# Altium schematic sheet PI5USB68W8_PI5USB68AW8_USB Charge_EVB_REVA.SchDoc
size 246 x 182 mm
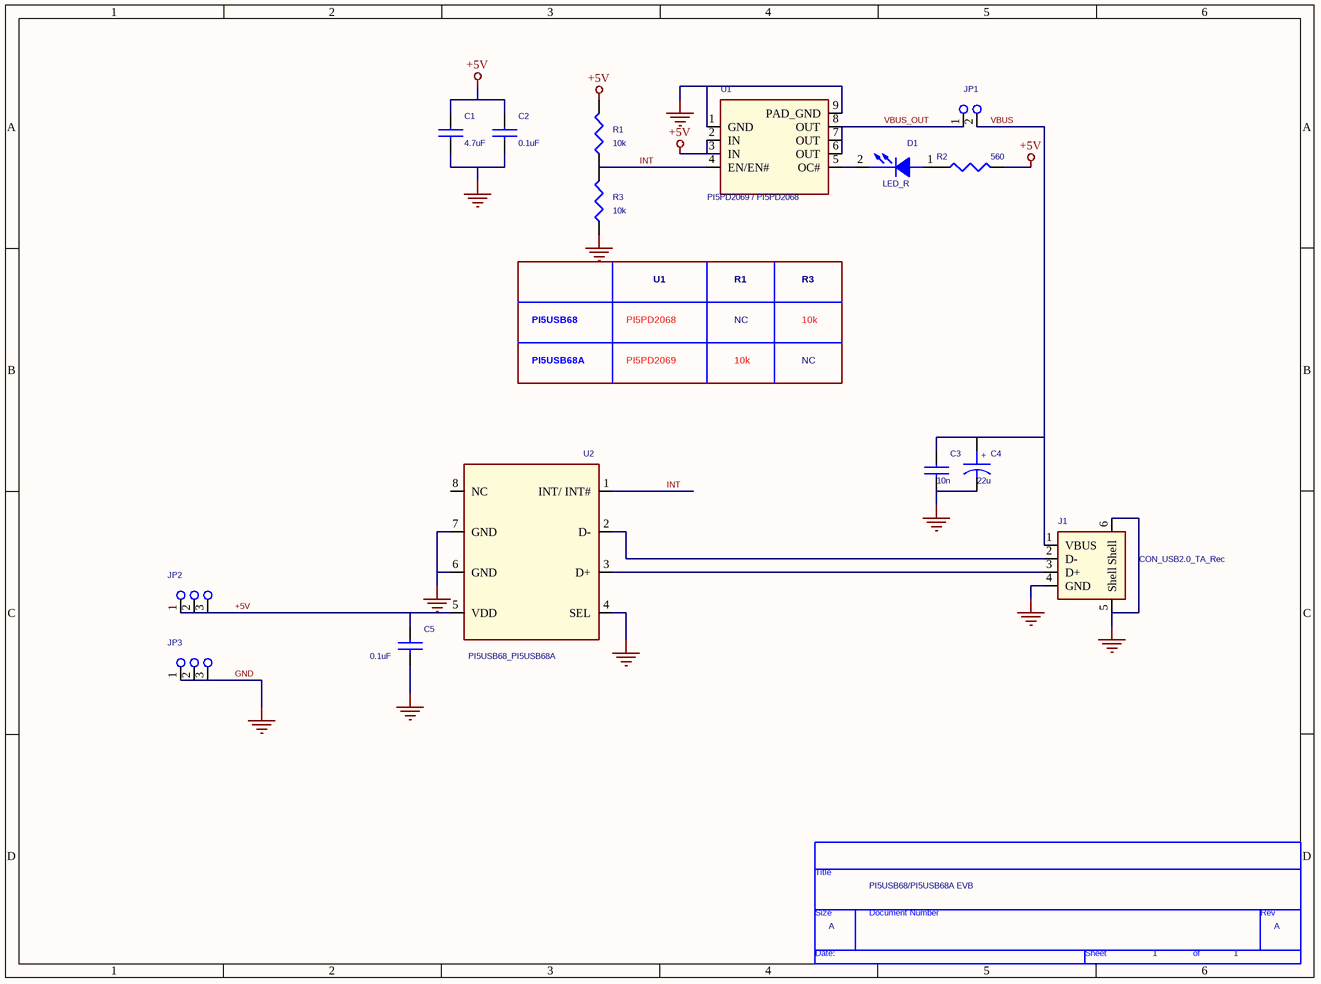
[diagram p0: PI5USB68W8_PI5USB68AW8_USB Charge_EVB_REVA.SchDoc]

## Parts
*  Page Count: 1  Page Size: A  Title: PI5USB68/PI5USB68A EVB  (hidden comment: TitleBlock0)  (graphical)
C1  4.7uF  [CC_0805]
C2  0.1uF  [CAP@CC_0805]
C3  10n  [CC_0402]
C4  22u  [CT_3528]
C5  0.1uF  [CAP@CC_0805]
D1  LED_R  [LED_0805]
J1  CON_USB2.0_TA_Rec  [CON_USB2.0_TA_Rec]
JP1  2x1 Pin Header  [2x1 Pin Header]  (value not drawn)
JP2  3x1 Pin Header  [3x1 Pin Header]  (value not drawn)
JP3  3x1 Pin Header  [3x1 Pin Header]  (value not drawn)
R1  10k  [R_0402]
R2  560  [R_0402]
R3  10k  [R_0402]
U1  PI5PD2069 / PI5PD2068  [SOIC8]
U2  PI5USB68_PI5USB68A  [SOIC8]

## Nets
+5V: C1.1 C2.1 C5.1 JP2.1 JP2.2 JP2.3 R1.2 R2.2 U1.2(IN) U1.3(IN) U2.5(VDD)
GND: C1.2 C2.2 C3.2 C4.2 C5.2 J1.4(GND) J1.5(Shell) J1.6(Shell) JP3.1 JP3.2 JP3.3 R3.1 U1.1(GND) U1.9(PAD_GND) U2.4(SEL) U2.6(GND) U2.7(GND)
INT: R1.1 R3.2 U1.4(EN/EN#) U2.1(INT/_INT#)
VBUS: C3.1 C4.1 J1.1(VBUS) JP1.2
VBUS_OUT: JP1.1 U1.6(OUT) U1.7(OUT) U1.8(OUT)
NetD1_1: D1.1(ANODE) R2.1
NetD1_2: D1.2(CATHODE) U1.5(OC#)
NetJ1_2: J1.2(D-) U2.2(D-)
NetJ1_3: J1.3(D+) U2.3(D+)

Not connected (* = marked no-connect by the designer): U2 8(NC)

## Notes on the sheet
- PI5USB68
- PI5PD2068
- U1
- NC
- R1
- R3
- 10k
- PI5USB68A
- PI5PD2069

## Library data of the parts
C1 = C_4.7u_0805
C2 C5 = C_4.7u_0805_Dup1
C3 = C_10n_0402
C4 = C_tan_22u_3528
D1 = LED_0805_R
R1-R3 = R_0402
U1 = PI90LV018A@SOIC8_0
U2 = PI6C2405A-1WE@SOIC8_0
